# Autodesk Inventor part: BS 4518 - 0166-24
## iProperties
Created: 2006-02
Part Number: BS 4518 - 0166-24
Material: Rubber
Description: Metric dimensions of toriodal sealing rings(O-rings) and their housings
Document SubType Name: Modeling
Standard: BS 4518
Designer: Andy Moles
Standards Organization: BSI
Language: en-US
Size Designation: 0166-24
Categories: <MemberInstance><Categories><Category DisplayName="Shaft Parts" InternalName="7f7aeb1f-a693-4053-b835-cee3144e0d98" Mnemonic="SHFT"><Category DisplayName="Seali
Density: 1 g/cm^3
Author: Andy Moles
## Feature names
1. Body [Revolution]
